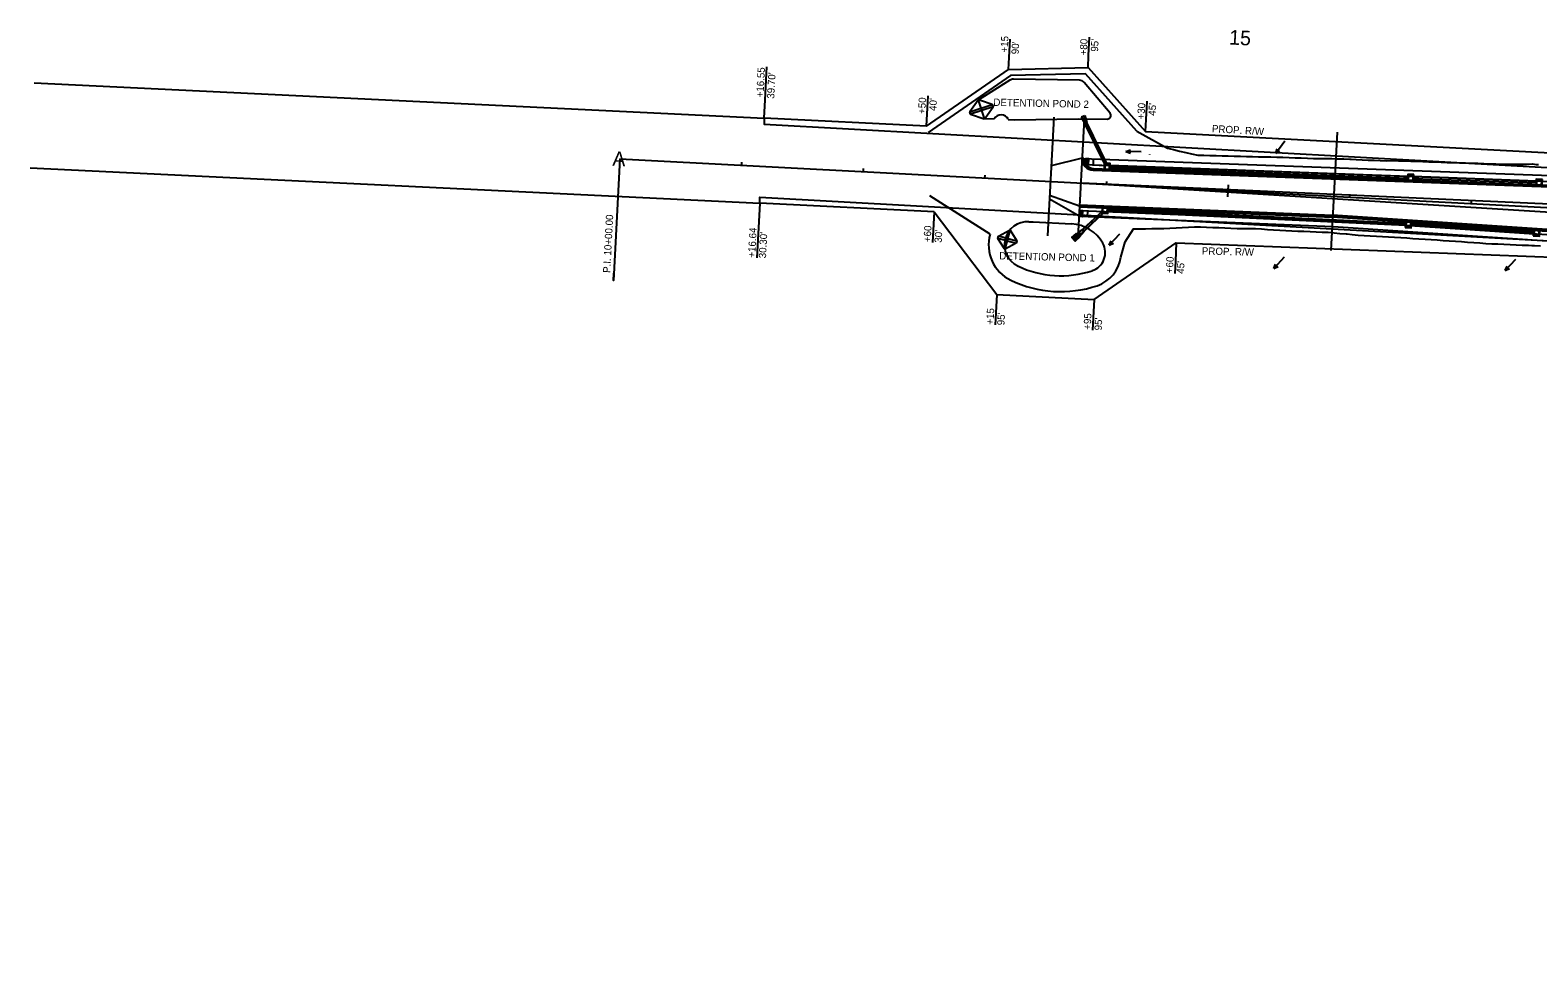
# Model space of a CAD drawing. Extents: x 670017 to 673226, y 705371 to 707498.
# Drawn here: x 670017 to 671255, y 705939 to 706712 of the extents above; entities that cross this region are included whole.
import ezdxf

# ---------------------------------------------------------------- set-up
doc = ezdxf.new("R2010")
doc.units = 0
for name, color, linetype in [('C-STRM-STRC', 7, 'Continuous'), ('EL L 264', 7, 'Continuous'), ('EL R 264', 7, 'Continuous'), ('R_Drainage Flow Lines', 7, 'Continuous'), ('R_Drainage Stage 1A', 7, 'Continuous'), ('R_Drainage Stage 2A', 7, 'Continuous'), ('R_Horz Alg', 7, 'Continuous'), ('R_Horz Alg Station', 7, 'Continuous'), ('R_Horz Alg Station Annot', 7, 'Continuous'), ('R_No Plot', 7, 'Continuous'), ('R_No Plot FOC', 7, 'Continuous'), ('R_Proposed Const Limits Stage 1A', 7, 'Continuous'), ('R_Proposed Const Limits Stage 2A', 7, 'Continuous'), ('R_Proposed Road Stage 1A', 7, 'Continuous'), ('R_Proposed Road Stage 2A', 7, 'Continuous'), ('R_Proposed Sidewalk Stage 1A', 7, 'Continuous'), ('R_Proposed Sidewalk Stage 2A', 7, 'Continuous'), ('R_ROW', 7, 'Continuous'), ('R_ROW Annot', 7, 'Continuous'), ('R_Striping', 7, 'Continuous'), ('R_Water Annot', 7, 'Continuous'), ('S_EXIST_ROW', 7, 'Continuous')]:
    doc.layers.add(name, color=color, linetype=linetype)

# ---------------------------------------------------------------- blocks, each defined once
blk = doc.blocks.new('FLOW ARROW')
at = {"layer": 'R_Water Annot'}
for p, q in [((-12.6, 0), (0, 0)), ((0, 0), (-3.8, 1.4)), ((0, 0), (-3.8, -1.4))]:
    blk.add_line(p, q, dxfattribs=at)
blk = doc.blocks.new('POND 1 STRC TO SCALE FOR PLANS')
at = {"layer": 'C-STRM-STRC'}
for points in [[(2044531.1, 2153463.3), (2044508.3, 2153442), (2044506.7, 2153442), (2044483.9, 2153463.3), (2044483.9, 2153469.4), (2044506.7, 2153490.7), (2044508.3, 2153490.7), (2044531.1, 2153469.4)], [(2044506.7, 2153490.7), (2044506.7, 2153442), (2044508.3, 2153442), (2044508.3, 2153490.7)]]:
    blk.add_lwpolyline(points, close=True, dxfattribs=at)
for points in [[(2044506.7, 2153469.4), (2044483.9, 2153469.4)], [(2044506.7, 2153463.3), (2044483.9, 2153463.3)], [(2044508.3, 2153469.4), (2044531.1, 2153469.4)], [(2044508.3, 2153463.3), (2044531.1, 2153463.3)]]:
    blk.add_lwpolyline(points, dxfattribs=at)

msp = doc.modelspace()

# ---------------------------------------------------------------- linework, layer by layer
at = {"layer": 'EL L 264'}
msp.add_line((670890.2, 706596.7), (671265.4, 706583), dxfattribs=at)
msp.add_line((670890.2, 706596.7), (671265.4, 706583), dxfattribs=at)
msp.add_arc((670890.6, 706606.2), 9.5, 176.9958, 268.0301, dxfattribs=at)
msp.add_arc((670890.6, 706606.2), 9.5, 176.9958, 268.0301, dxfattribs=at)
at = {"layer": 'EL R 264'}
for p, q in [((670879.1, 706568.2), (671086.9, 706559.8)), ((671086.9, 706559.8), (671263.5, 706548))]:
    msp.add_line(p, q, dxfattribs=at)
at = {"layer": 'R_Drainage Stage 1A'}
for p, q in [((670880.5, 706640.3), (670880.3, 706640.2)), ((670880.3, 706640.2), (670883.4, 706635.2)), ((670881.6, 706639.1), (670880.3, 706640.2)), ((670883.1, 706641.5), (670880.5, 706640.3)), ((670880.5, 706640.3), (670883.5, 706635.5)), ((670880.5, 706640.3), (670881.6, 706639.1)), ((670883.1, 706641.5), (670883.3, 706641.6)), ((670883.1, 706641.5), (670884.8, 706636.1)), ((670883.1, 706641.5), (670883.2, 706639.9)), ((670883.2, 706639.9), (670883.3, 706641.6)), ((670883.3, 706641.6), (670885.1, 706636)), ((670883.6, 706635.3), (670883.4, 706635.2)), ((670899.8, 706601.6), (670883.4, 706635.2)), ((670884.8, 706636.1), (670883.5, 706635.5)), ((670883.6, 706635.3), (670883.5, 706635.5)), ((670884.9, 706635.9), (670883.6, 706635.3)), ((670899.9, 706601.8), (670883.6, 706635.3)), ((670884.9, 706635.9), (670884.8, 706636.1)), ((670885.1, 706636), (670884.9, 706635.9)), ((670901.6, 706601.7), (670884.9, 706635.9)), ((670901.8, 706601.7), (670885.1, 706636)), ((671149, 706590), (670903.7, 706598.9)), ((671149, 706589.8), (670903.7, 706598.8)), ((671149.1, 706591.6), (670903.8, 706600.6)), ((671149.1, 706591.5), (670903.8, 706600.4)), ((671254.5, 706586.1), (671153, 706589.8)), ((671254.5, 706586), (671153, 706589.7)), ((671254.6, 706587.8), (671153.1, 706591.5)), ((671254.5, 706587.6), (671153.1, 706591.3))]:
    msp.add_line(p, q, dxfattribs=at)
for points in [[(670821.9, 706670.6), (670795.7, 706654.2), (670800.7, 706639.1), (670809, 706639)], [(670879.1, 706670.6), (670824.7, 706671.4)], [(670904.1, 706643.6), (670882.8, 706668.8)], [(670795.7, 706654.2), (670788.9, 706644.6), (670789.2, 706643.6), (670789.5, 706642.7), (670800.7, 706639)], [(670801.2, 706639.2), (670802, 706640.3), (670808.1, 706648.8), (670807.4, 706650.7), (670797.7, 706653.9), (670796.2, 706654.4)], [(670820.5, 706638.5), (670825.6, 706638.2), (670878, 706638.8), (670901.8, 706638.7)]]:
    msp.add_lwpolyline(points, dxfattribs=at)
for points in [[(670788.9, 706644.6), (670807.4, 706650.7), (670808.1, 706648.8), (670789.5, 706642.7)], [(670899.2, 706597.3), (670904.1, 706597.2), (670904.3, 706602.2), (670899.3, 706602.3)], [(670899.7, 706597.8), (670903.7, 706597.7), (670903.8, 706601.7), (670899.8, 706601.8)], [(670904.2, 706599.2), (670908.2, 706599), (670908.1, 706597), (670904.1, 706597.2)], [(670904.2, 706598.7), (670907.7, 706598.5), (670907.7, 706597.5), (670904.2, 706597.7)], [(671153.6, 706593.1), (671148.6, 706593.2), (671148.5, 706588.2), (671153.5, 706588.1)], [(671153.1, 706592.6), (671149.1, 706592.7), (671149, 706588.7), (671153, 706588.6)], [(671153.5, 706590.1), (671157.5, 706589.9), (671157.5, 706587.9), (671153.5, 706588.1)], [(671153.5, 706589.6), (671157, 706589.4), (671157, 706588.4), (671153.5, 706588.6)], [(671259.1, 706589.2), (671254.1, 706589.4), (671253.9, 706584.4), (671258.9, 706584.2)], [(671258.6, 706588.7), (671254.6, 706588.9), (671254.4, 706584.9), (671258.4, 706584.7)]]:
    msp.add_lwpolyline(points, close=True, dxfattribs=at)
for centre, radius, start, end in [((670824.6, 706666.4), 5, 89.1663, 122.0798), ((670879, 706665.6), 5, 40.1997, 89.1663), ((670814.6, 706635.6), 6.58, 26.5492, 149.1995), ((670882.3, 706639.8), 0.957, 224.4231, 5.6482), ((670901.8, 706641.7), 3, 269.6273, 40.1997)]:
    msp.add_arc(centre, radius, start, end, dxfattribs=at)
at = {"layer": 'R_Drainage Stage 2A'}
for p, q in [((671147.1, 706553.1), (670901.9, 706564.7)), ((671147.1, 706553), (670901.9, 706564.5)), ((670897.8, 706563.2), (670881.4, 706548)), ((670897.8, 706563), (670881.5, 706547.9)), ((670898.8, 706561.9), (670882.6, 706546.8)), ((670899.1, 706561.9), (670882.7, 706546.7)), ((671147, 706551.5), (670901.8, 706563)), ((671147, 706551.3), (670901.8, 706562.8)), ((671252.4, 706546), (671151.1, 706552.7)), ((670876.7, 706544.6), (670881.4, 706548)), ((670878.3, 706545.1), (670876.7, 706544.6)), ((670876.8, 706544.4), (670876.7, 706544.6)), ((670876.8, 706544.4), (670881.4, 706547.7)), ((670876.8, 706544.4), (670878.3, 706545.1)), ((670876.8, 706544.4), (670878.8, 706542.3)), ((670878.8, 706542.3), (670882.3, 706546.7)), ((670878.8, 706542.3), (670879.5, 706543.7)), ((670878.8, 706542.3), (670878.9, 706542.2)), ((670878.9, 706542.2), (670882.7, 706546.7)), ((670879.5, 706543.7), (670878.9, 706542.2)), ((670881.4, 706548), (670881.6, 706547.8)), ((670881.6, 706547.8), (670881.4, 706547.7)), ((670881.4, 706547.7), (670882.4, 706546.6)), ((670881.6, 706547.8), (670882.5, 706546.8)), ((670882.5, 706546.8), (670882.4, 706546.6)), ((670882.5, 706546.8), (670882.7, 706546.7)), ((671252.3, 706544.5), (671151, 706551.3)), ((671252.3, 706544.3), (671151, 706551.1))]:
    msp.add_line(p, q, dxfattribs=at)
for points in [[(670897.3, 706561.5), (670902.3, 706561.3), (670902.5, 706566.3), (670897.5, 706566.5)], [(670897.8, 706561.9), (670901.8, 706561.8), (670901.9, 706565.8), (670897.9, 706565.9)], [(671146.4, 706549.8), (671151.4, 706549.5), (671151.7, 706554.5), (671146.7, 706554.8)], [(671146.9, 706550.3), (671150.9, 706550), (671151.2, 706554), (671147.2, 706554.3)], [(671151.7, 706554.4), (671155.7, 706554.2), (671155.6, 706552.2), (671151.6, 706552.5)], [(671151.7, 706554), (671155.2, 706553.8), (671155.1, 706552.8), (671151.6, 706553)], [(670876.4, 706544.8), (670879.1, 706541.9), (670875.5, 706538.5), (670872.8, 706541.4)], [(671251.7, 706542.8), (671256.7, 706542.5), (671257, 706547.5), (671252, 706547.8)], [(671252.2, 706543.3), (671256.2, 706543), (671256.5, 706547), (671252.5, 706547.3)]]:
    msp.add_lwpolyline(points, close=True, dxfattribs=at)
msp.add_lwpolyline([(670837.4, 706554.5), (670840.9, 706554.3), (670872.5, 706552.6)], dxfattribs=at)
for centre, radius, start, end in [((670836.4, 706535.4), 19.1, 86.9246, 244.8077), ((670870.8, 706521.3), 31.4, 29.591, 86.9246), ((670878.7, 706544.2), 0.957, 332.2662, 113.4914), ((670884.5, 706529.1), 15.6, 288.3972, 29.591), ((670863.6, 706591.8), 81.7, 244.3202, 288.3972)]:
    msp.add_arc(centre, radius, start, end, dxfattribs=at)
for centre, start_param, end_param in [((670873.9, 706540.9), 3.601691, 4.056701), ((670873.9, 706540.9), 5.467768, 8.991439), ((670874.9, 706541.8), 3.535072, 9.058057), ((670875.5, 706539.1), 1.281641, 3.914409), ((670876.5, 706539.9), 1.309554, 5.00039), ((670877.6, 706540.7), 1.438249, 4.871695), ((670878.5, 706541.5), 1.465244, 4.8447)]:
    msp.add_ellipse(centre, major_axis=(0.827, -0.938), ratio=0.517889, start_param=start_param, end_param=end_param, dxfattribs=at)
for centre in [(670875.9, 706542.6), (670876.9, 706543.4)]:
    msp.add_ellipse(centre, major_axis=(0.827, -0.938), ratio=0.517889, dxfattribs=at)
at = {"layer": 'R_Horz Alg'}
msp.add_line((670501.5, 706606), (672734.8, 706488.8), dxfattribs=at)
at = {"layer": 'R_Horz Alg Station'}
for points in [[(670501.5, 706606), (670496.3, 706506.2), (670496.6, 706512.2)], [(670601.5, 706603.3), (670601.4, 706600.8)], [(670701.4, 706598.1), (670701.2, 706595.6)], [(670801.2, 706592.8), (670801.1, 706590.3)], [(670901.1, 706587.6), (670901, 706585.1)], [(671001.1, 706584.8), (671000.6, 706574.8)], [(671100.8, 706577.1), (671100.7, 706574.6)], [(671200.7, 706571.9), (671200.6, 706569.4)]]:
    msp.add_lwpolyline(points, dxfattribs=at)
at = {"layer": 'R_No Plot'}
msp.add_line((670936.5, 706609.6), (670936.5, 706609.5), dxfattribs=at)
for points in [[(670857.8, 706640.2), (670852.7, 706542.9)], [(670882.8, 706638.8), (670877.7, 706541.6)], [(671090.5, 706627.9), (671085.4, 706530.7)]]:
    msp.add_lwpolyline(points, dxfattribs=at)
at = {"layer": 'R_No Plot FOC'}
for p, q in [((670890.3, 706597.7), (671265.4, 706584)), ((670879, 706567.2), (671086.9, 706558.8)), ((671293.3, 706545), (671086.8, 706558.8))]:
    msp.add_line(p, q, dxfattribs=at)
msp.add_arc((670890.6, 706606.2), 8.5, 176.9958, 268.0301, dxfattribs=at)
at = {"layer": 'R_Proposed Const Limits Stage 1A'}
for points in [[(670926.2, 706628.8), (670883.8, 706675.9), (670822.4, 706674.4), (670754.7, 706627.8)], [(670926.2, 706628.8), (670951.3, 706614.9), (670956.2, 706613.7), (670961.2, 706612.5), (670966.2, 706611.3), (670971.1, 706610.2), (670976.1, 706609.1)], [(670976.1, 706609), (670981.1, 706609), (670986.1, 706608.9), (670991.1, 706608.8), (670996.1, 706608.6), (671001.1, 706608.5), (671006.1, 706608.3), (671011.1, 706608.2), (671016.1, 706608), (671021.1, 706607.9), (671026.1, 706607.8), (671031.1, 706607.7), (671036.1, 706607.7), (671041.1, 706607.5), (671046.1, 706607.4), (671051.1, 706607.2), (671056.1, 706607), (671061.1, 706606.8), (671066.1, 706606.7), (671071.1, 706606.5), (671076.1, 706606.4), (671081.1, 706606.3), (671086.1, 706606.3), (671089.1, 706606.2), (671091.1, 706606.2), (671096.1, 706606.1), (671101.1, 706605.8), (671102.1, 706605.8), (671106.1, 706605.6), (671111.1, 706605.4), (671116.1, 706605.1), (671121, 706604.9), (671126, 706604.7), (671131, 706604.4), (671136, 706604.6), (671141, 706604.5), (671146, 706604.4), (671151, 706604.3), (671156, 706604.1), (671161, 706603.9), (671166, 706603.7), (671171, 706603.6), (671176, 706603.4), (671181, 706603.2), (671186, 706603), (671191, 706602.9), (671196, 706602.7), (671201, 706602.6), (671206, 706602.4), (671211, 706602.3), (671216, 706602.1), (671221, 706602), (671226, 706601.8), (671231, 706601.7), (671236, 706601.7), (671241, 706601.7), (671246, 706601.8), (671251, 706602), (671254, 706601.5), (671256, 706601.4)]]:
    msp.add_lwpolyline(points, dxfattribs=at)
at = {"layer": 'R_Proposed Const Limits Stage 2A'}
msp.add_line((670805.5, 706544.3), (670756.2, 706575.8), dxfattribs=at)
for points in [[(670912.9, 706525.4), (670916.6, 706537.9), (670923.3, 706548.6), (670928.3, 706548.5), (670933.3, 706548.6), (670938.3, 706548.8), (670943.3, 706548.8), (670948.3, 706548.9), (670953.3, 706549.2), (670958.4, 706549.5), (670963.4, 706549.8), (670968.4, 706550.1), (670973.4, 706550.3), (670978.4, 706550.2)], [(670978.4, 706550.2), (670983.4, 706550), (670988.4, 706549.8), (670993.4, 706549.6), (670998.4, 706549.4), (671003.4, 706549.1), (671008.4, 706549), (671013.4, 706548.8), (671018.4, 706548.9), (671023.4, 706548.8), (671028.4, 706548.6), (671033.4, 706548.2), (671038.4, 706547.9), (671043.4, 706547.6), (671048.4, 706547.3), (671053.3, 706547), (671058.3, 706546.8), (671063.3, 706546.6), (671068.3, 706546.3), (671073.3, 706546.1), (671078.3, 706546), (671083.3, 706545.8), (671086.3, 706545.6), (671088, 706545.4), (671092.9, 706544.9), (671097.9, 706544.5), (671098.9, 706544.4), (671102.9, 706544), (671107.9, 706543.5), (671112.9, 706543.1), (671117.8, 706542.8), (671122.8, 706542.6), (671127.8, 706542.3), (671132.8, 706542), (671137.8, 706541.7), (671142.8, 706541.4), (671147.8, 706541.1), (671152.8, 706540.8), (671157.8, 706540.5), (671162.8, 706540.2), (671167.8, 706539.9), (671172.8, 706539.5), (671177.7, 706539.1), (671182.7, 706538.8), (671187.7, 706538.4), (671192.7, 706538.1), (671197.7, 706537.7), (671202.7, 706537.4), (671207.7, 706537), (671212.7, 706536.7), (671217.7, 706536.4), (671222.6, 706536.2), (671227.6, 706535.9), (671232.6, 706535.7), (671237.6, 706535.5), (671242.6, 706535.3), (671247.6, 706535.1), (671250.6, 706535), (671252.6, 706534.9), (671257.6, 706534.8)]]:
    msp.add_lwpolyline(points, dxfattribs=at)
for centre, radius, start, end in [((670836.4, 706535.4), 32.1, 163.9795, 244.6998), ((670884.5, 706529.1), 28.6, 288.3972, 352.6895), ((670863.6, 706591.8), 94.7, 244.3506, 288.3972)]:
    msp.add_arc(centre, radius, start, end, dxfattribs=at)
at = {"layer": 'R_Proposed Road Stage 1A'}
for p, q in [((670881.1, 706606.7), (670855.7, 706600.4)), ((670881.1, 706606.7), (670882.6, 706606.6)), ((670890.2, 706596.7), (671265.4, 706583)), ((670890.3, 706598.2), (671265.4, 706584.5))]:
    msp.add_line(p, q, dxfattribs=at)
for radius in [9.5, 8]:
    msp.add_arc((670890.6, 706606.2), radius, 176.9958, 268.0301, dxfattribs=at)
at = {"layer": 'R_Proposed Road Stage 2A'}
for p, q in [((670879, 706567.2), (670854.4, 706576.1)), ((670879.1, 706568.2), (670879, 706566.7)), ((670879, 706566.7), (671086.8, 706558.3)), ((670879.1, 706568.2), (671086.9, 706559.8)), ((671293.3, 706544.5), (671086.8, 706558.3)), ((671293.4, 706546), (671086.9, 706559.8))]:
    msp.add_line(p, q, dxfattribs=at)
at = {"layer": 'R_Proposed Sidewalk Stage 1A'}
for p, q in [((670881.1, 706606.5), (671266.2, 706592.4)), ((670886.3, 706606.3), (670886.1, 706601.3)), ((670890.3, 706606.1), (670890.1, 706601.2)), ((670882.3, 706601.4), (671266, 706587.5)), ((670895.1, 706601), (671266, 706587.5))]:
    msp.add_line(p, q, dxfattribs=at)
msp.add_lwpolyline([(670884.1, 706601.4), (670884.3, 706606.4), (670886.3, 706606.3), (670886.1, 706601.3)], close=True, dxfattribs=at)
for centre in [(670884.6, 706603), (670884.6, 706602.4), (670884.6, 706601.8), (670884.7, 706605.4), (670884.7, 706604.8), (670884.7, 706604.2), (670884.6, 706603.6), (670884.7, 706606), (670885.2, 706602.9), (670885.2, 706602.3), (670885.2, 706601.7), (670885.3, 706605.3), (670885.3, 706604.7), (670885.3, 706604.1), (670885.2, 706603.5), (670885.3, 706605.9), (670885.8, 706602.9), (670885.8, 706602.3), (670885.8, 706601.7), (670885.9, 706605.3), (670885.9, 706604.7), (670885.9, 706604.1), (670885.8, 706603.5), (670885.9, 706605.9)]:
    msp.add_circle(centre, 0.165, dxfattribs=at)
at = {"layer": 'R_Proposed Sidewalk Stage 2A'}
for p, q in [((670879.3, 706558.7), (670854.3, 706573.1)), ((671087.4, 706550.2), (670879.3, 706558.7)), ((670879.5, 706563.7), (671087.7, 706555.2)), ((670881.5, 706563.6), (670881.3, 706558.6)), ((670885.5, 706563.4), (670885.3, 706558.4)), ((671289.4, 706541.8), (671087.7, 706555.2)), ((671289.1, 706536.8), (671087.4, 706550.2))]:
    msp.add_line(p, q, dxfattribs=at)
msp.add_lwpolyline([(670879.3, 706558.7), (670879.5, 706563.7), (670881.5, 706563.6), (670881.3, 706558.6)], close=True, dxfattribs=at)
for centre in [(670879.7, 706559.7), (670879.7, 706559.1), (670879.8, 706562.1), (670879.8, 706561.5), (670879.7, 706560.9), (670879.7, 706560.3), (670879.8, 706563.3), (670879.8, 706562.7), (670880.3, 706559.6), (670880.3, 706559), (670880.4, 706562), (670880.4, 706561.4), (670880.3, 706560.8), (670880.3, 706560.2), (670880.4, 706563.2), (670880.4, 706562.6), (670880.9, 706559.6), (670880.9, 706559), (670881, 706562), (670881, 706561.4), (670880.9, 706560.8), (670880.9, 706560.2), (670881, 706563.2), (670881, 706562.6)]:
    msp.add_circle(centre, 0.165, dxfattribs=at)
at = {"layer": 'R_ROW'}
for points in [[(670753.3, 706632.9), (670820.8, 706679.4), (670886, 706681), (670933.3, 706628.4), (671562.4, 706595.4), (671640.2, 706635.1), (671682.6, 706708.6)], [(670753.3, 706632.9), (670620, 706639.6)], [(670759.6, 706562.5), (670616.4, 706569.7)], [(670759.6, 706562.5), (670811.1, 706494.7), (670891, 706490.5), (670958.5, 706537), (671303.3, 706523.9), (671422.4, 706502.6), (671542.5, 706501.3), (671626.3, 706476.9), (671666.4, 706404.1), (671678.5, 706328.8), (671669.1, 706086.5), (671607.5, 706046.1), (671609.6, 705970.9), (671668.4, 705938.6)]]:
    msp.add_lwpolyline(points, dxfattribs=at)
at = {"layer": 'R_ROW Annot'}
for points in [[(670820.8, 706679.4), (670821.3, 706689.4), (670822.1, 706704.4)], [(670886, 706681), (670886.5, 706691), (670887.3, 706706)], [(670620, 706639.6), (670620.8, 706654.6), (670622.2, 706681.5)], [(670753.3, 706632.9), (670754.1, 706647.9), (670754.6, 706657.9)], [(670933.3, 706628.4), (670933.8, 706638.4), (670934.6, 706653.4)], [(670616.4, 706569.7), (670615.6, 706554.7), (670614, 706524.7)], [(670759.6, 706562.5), (670759.1, 706552.5), (670758.3, 706537.5)], [(670958.5, 706537), (670957.7, 706522), (670957.2, 706512)], [(670811.1, 706494.7), (670810.3, 706479.7), (670809.8, 706469.7)], [(670891, 706490.5), (670890.2, 706475.5), (670889.7, 706465.5)]]:
    msp.add_lwpolyline(points, dxfattribs=at)
at = {"layer": 'R_Striping'}
for p in [(671265.3, 706569), (671284.1, 706561)]:
    msp.add_line(p, (670881, 706586.1), dxfattribs=at)
at = {"layer": 'S_EXIST_ROW'}
for points in [[(670020.6, 706668.5), (670620, 706639.6), (670619.9, 706634.6), (671728.2, 706573.3), (673225.9, 706490.5)], [(670017.2, 706598.6), (670616.4, 706569.7), (670616.5, 706574.7), (671724.9, 706513.4), (673222.6, 706430.6)]]:
    msp.add_lwpolyline(points, dxfattribs=at)

# ---------------------------------------------------------------- block references
at = {"layer": 'R_Drainage Flow Lines'}
for p, rotation in [((671040.2, 706610.4), -126.70314512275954), ((670917.1, 706612.1), 178.67203369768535), ((670903.3, 706535.1), -132.9212970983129), ((671038.5, 706516), -132.9212970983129), ((671228.6, 706514.3), -132.9212970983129)]:
    msp.add_blockref('FLOW ARROW', p, dxfattribs=dict(at, rotation=rotation))
at = {"layer": 'R_Drainage Stage 2A', "xscale": 0.32808333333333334, "yscale": 0.32808333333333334, "rotation": -14.641555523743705}
msp.add_blockref('POND 1 STRC TO SCALE FOR PLANS', (-156753.6, 192517.7), dxfattribs=at)

# ---------------------------------------------------------------- texts
at = {"layer": 'R_Horz Alg'}
msp.add_text('A', height=12, rotation=356.9958, dxfattribs=at).set_placement((670495.2, 706600.4))
at = {"layer": 'R_Horz Alg Station Annot'}
for s, height, rotation, p in [('15', 12, 356.9958, (671001.7, 706700)), ('P.I. 10+00.00', 6, 86.9958, (670493.6, 706512.3))]:
    msp.add_text(s, height=height, rotation=rotation, dxfattribs=at).set_placement(p)
at = {"layer": 'R_ROW Annot'}
for s, rotation, p in [('+15', 86.9958, (670820, 706693.2)), ("90'", 86.9958, (670829, 706691.8)), ('+80', 86.9958, (670885, 706690.9)), ("95'", 86.9958, (670894.2, 706693.9)), ('+16.55', 86.9958, (670619.4, 706656.4)), ("39.70'", 86.9958, (670628.3, 706655.3)), ('+50', 86.9958, (670752.3, 706642.8)), ("40'", 86.9958, (670761.4, 706645.3)), ('DETENTION POND 2', 358.7327, (670808.2, 706649.6)), ('+30', 86.9958, (670932.3, 706638.3)), ("45'", 86.9958, (670941.5, 706641.3)), ('PROP. R/W', 356.6321, (670987.6, 706628)), ('+16.64', 86.9958, (670612.6, 706524.8)), ("30.30'", 86.9958, (670621.5, 706524.3)), ('+60', 86.9958, (670756.8, 706537.6)), ("30'", 86.9958, (670765.8, 706537.1)), ('DETENTION POND 1', 358.7327, (670813, 706523.5)), ('PROP. R/W', 358.7327, (670979.4, 706527.5)), ('+60', 86.9958, (670955.7, 706512.1)), ("45'", 86.9958, (670964.7, 706511.6)), ('+15', 86.9958, (670808.3, 706469.8)), ("95'", 86.9958, (670817.3, 706469.3)), ('+95', 86.9958, (670888.2, 706465.6)), ("95'", 86.9958, (670897.2, 706465.1))]:
    msp.add_text(s, height=6, rotation=rotation, dxfattribs=at).set_placement(p)

doc.saveas('drawing.dxf')
